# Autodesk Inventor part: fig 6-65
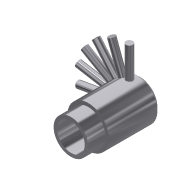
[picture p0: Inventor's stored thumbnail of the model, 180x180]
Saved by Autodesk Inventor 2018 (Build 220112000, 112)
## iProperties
Shininess: 77.0
Angle Display Precision: 2
Document Length Units: 11269
Document Angle Units: 11279
Document Time Units: 11290
Document Mass Units: 11283
Document Length Units Precision: 3
Document Angle Units Precision: 2
Compacted: True
Created: 2001-12
Part Number: fig 6-65
Document SubType Name: Modeling
Designer: Renu Muthoo
Density: 1 g/cm^3
Material: Generic
Appearance: Metal-AL-6061 (Polished)
Density: 0.0
Volumn: 0.0
Area: 0.0
PropertySet Name: Model Information
Control State: 0
Master: False
Checked Out: False
Author: Renu Muthoo
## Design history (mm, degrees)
sketch "Sketch2"
  geometry: L1 (-9.573, -4.327)-(-9.573, -5.327); L2 (-9.573, -5.327)-(-4.573, -5.327); L3 (-4.573, -5.327)-(-4.573, -6.327); L4 (-4.573, -6.327)-(9.427, -6.327); L5 (9.427, -6.327)-(10.427, -5.327); L6 (10.427, -5.327)-(10.427, -4.327); L7 (10.427, -4.327)-(-9.573, -4.327); L8 (-13.687, -0.327)-(14, -0.327)
  constraints: 16 end point, 5 parallel, 1 perpendicular, 1 vertical
  dimensions: "d9" = 20 distance of L6.end L1.start; "d10" = 5 distance of L1.end L2.end; "d11" = 12 diameter of L4 L8; "d12" = 10 diameter of L2 L8; "d13" = 8 diameter of L7 L8; "d14" = 45 deg angle of L5 L4; "d15" = 1 horizontal distance of L5.end L4.end
revolve "Revolution2" sketch "Sketch2" stored, may be unused: angle "d16" = 90 deg
workplane "Work Plane1"
workplane "Work Plane2"
sketch "Sketch3"
  geometry: L1 (-4, 8)-(4, 8) reference; C1 r 1 at (-0.098, 5)
  constraints: 1 centre point
  dimensions: "d18" = 3 distance from line of L1 C1.centre; "d19" = 2 diameter of C1
extrude "Extrusion1" join sketch "Sketch3" distance "d20" = 10; taper "d21" = 0 deg
pattern_circular "Circular Pattern3" dims angle "d29" = 20 deg
body "Solid1"
other parameters: "d17" = -1
